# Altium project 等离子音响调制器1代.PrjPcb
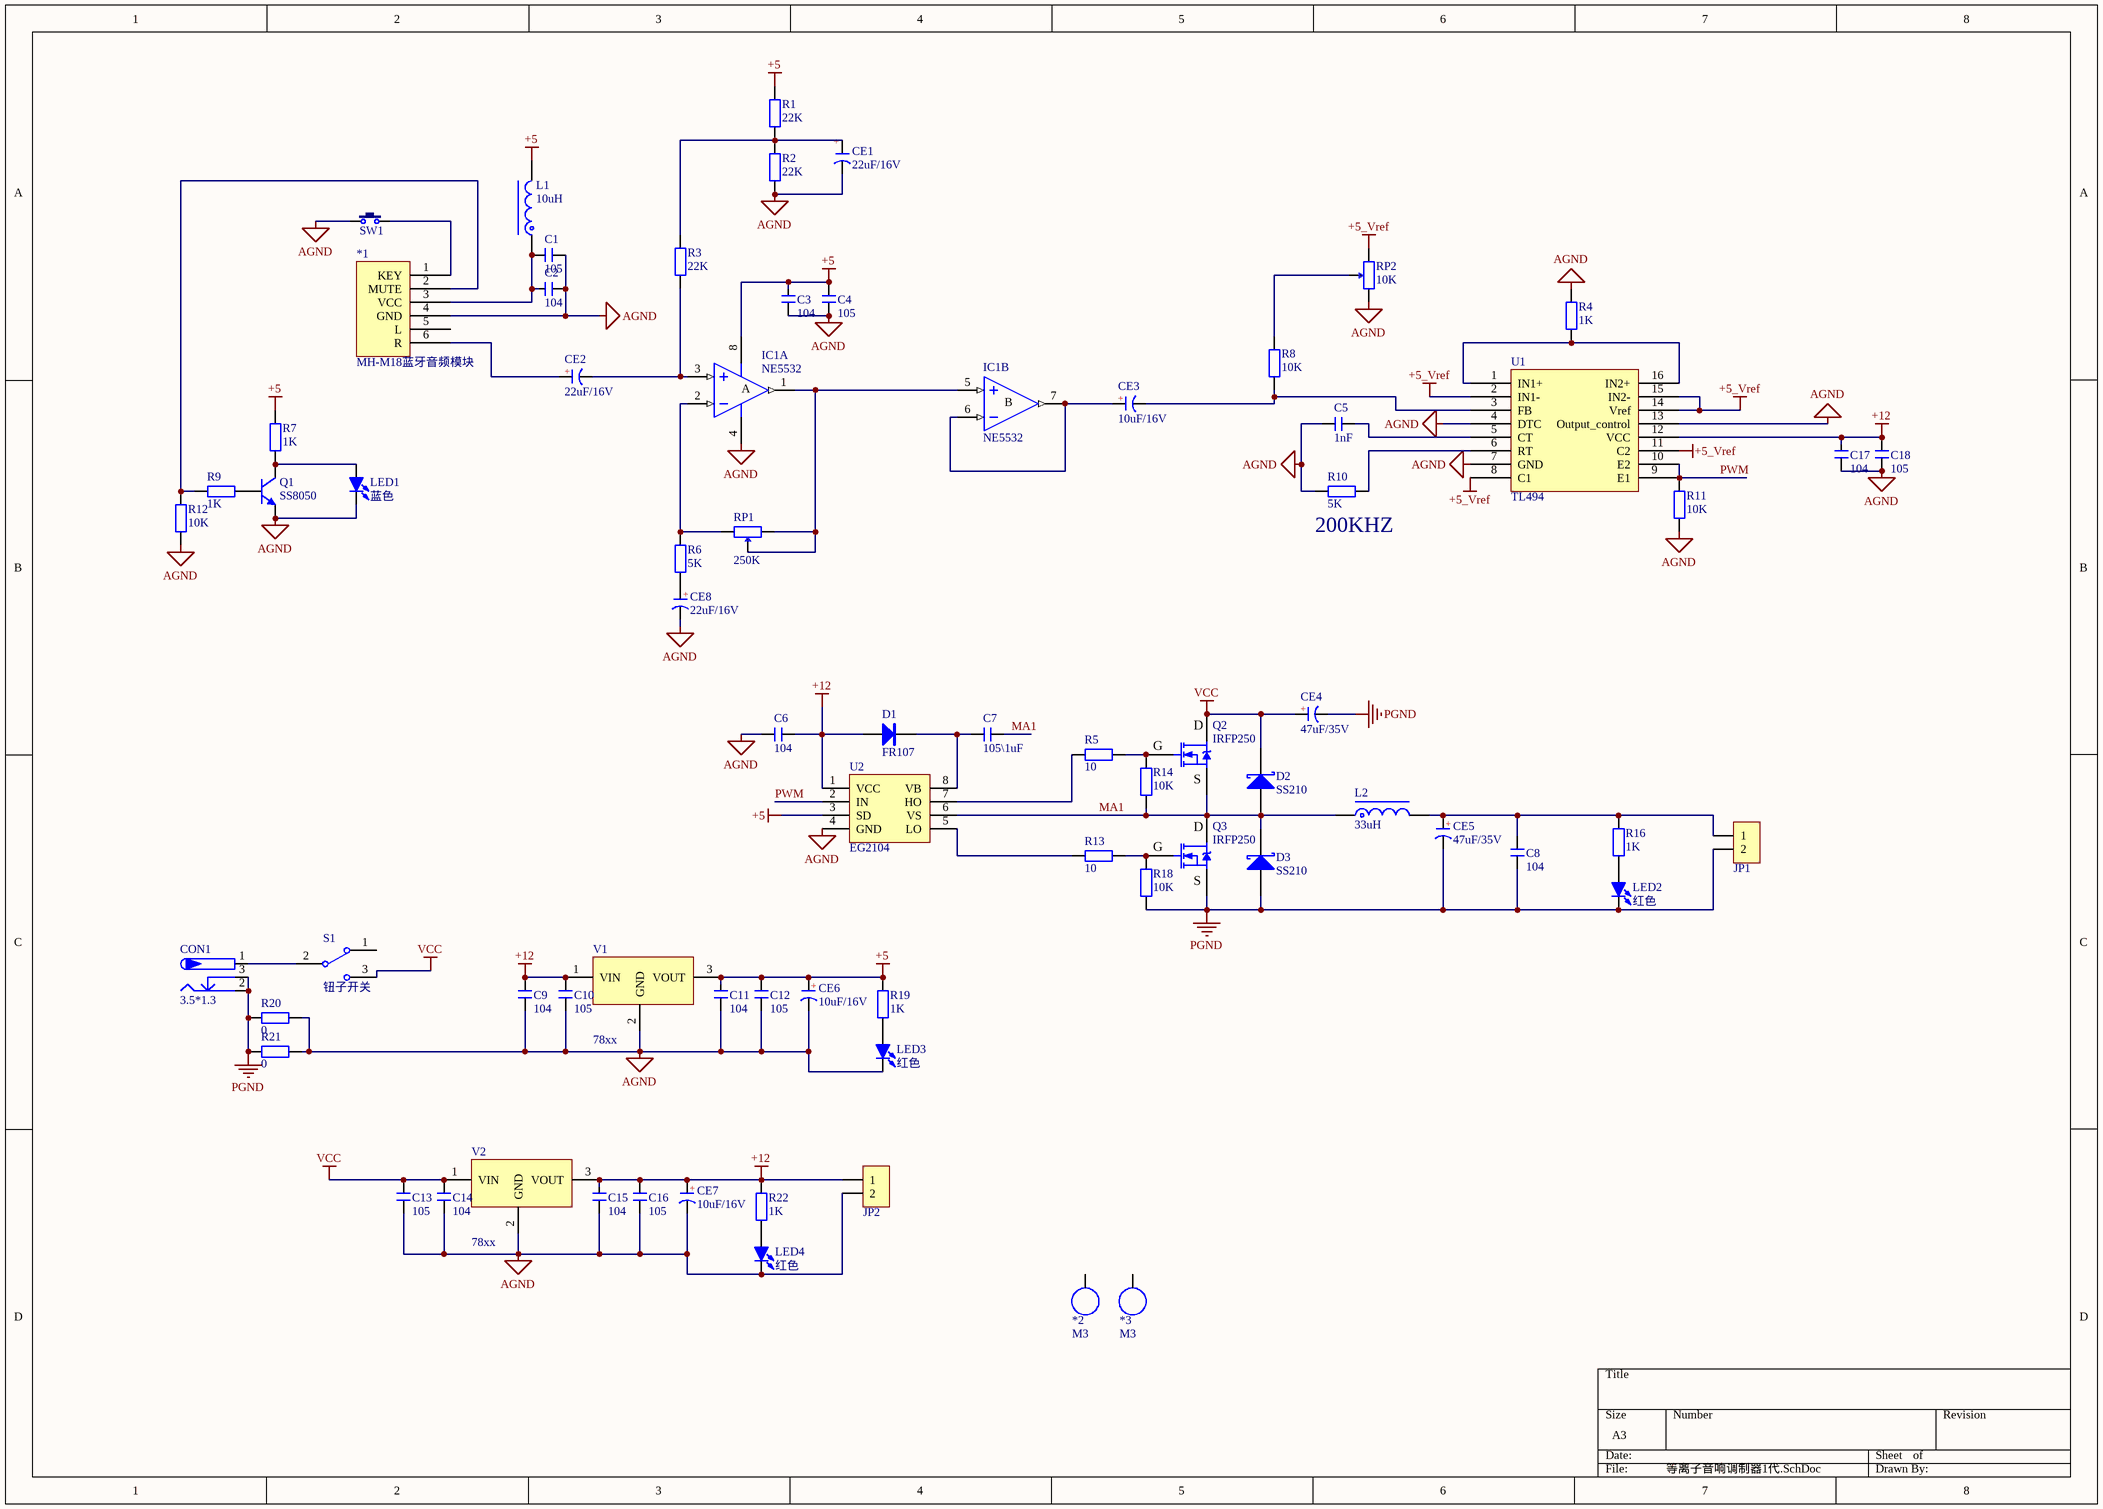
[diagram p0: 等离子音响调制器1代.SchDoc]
1 sheet, 73 parts. Net scope: global (net labels, ports and power ports of the same name join across sheets).
Board file: 等离子音响调制器.PcbDoc

## Sheet 等离子音响调制器1代.SchDoc
size A3; SheetNumber: 1; SheetTotal: 1

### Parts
*1  MH-M18蓝牙音频模块  [MH-M18蓝牙音频模块]
*2  M3  [M3 125X200]
*3  M3  [M3 125X200]
C1  105  [C 0805_L]
C2  104  [C 0603_L]
C3  104  [C 0603_L]
C4  105  [C 0805_L]
C5  1nF  [C 0603_L]
C6  104  [C 0603_L]
C7  105\1uF  [C 0805_L]
C8  104  [C 0805_L]
C9  104  [C 0603_L]
C10  105  [C 0805_L]
C11  104  [C 0603_L]
C12  105  [C 0805_L]
C13  105  [C 0805_L]
C14  104  [C 0603_L]
C15  104  [C 0603_L]
C16  105  [C 0805_L]
C17  104  [C 0603_L]
C18  105  [C 0805_L]
CE1  22uF/16V  [CAP 2.0*5*11]
CE2  22uF/16V  [CAP 2.0*5*11]
CE3  10uF/16V  [CAP 2.0*5*11]
CE4  47uF/35V  [CAP 5.0*10*12.5]
CE5  47uF/35V  [CAP 3.5*8*11.5]
CE6  10uF/16V  [CAP 3.5*8*11.5 - GD]
CE7  10uF/16V  [CAP 3.5*8*11.5 - GD]
CE8  22uF/16V  [CAP 2.0*5*11]
CON1  3.5*1.3  [DC-005]
D1  FR107  [SOD-123]
D2  SS210  [SMA]
D3  SS210  [SMA]
IC1  NE5532  [DIP8-300]  (parts A,B of 2)
JP1  HDR-1X2  [KF128-5.08-2P]  (value not drawn)
JP2  HDR-1X2  [XH2.54-LI-2P]  (value not drawn)
L1  10uH  [PK0810]
L2  33uH  [65125]
LED1  蓝色  [LED 0603Y]
LED2  红色  [LED 0603Y]
LED3  红色  [LED 0603Y]
LED4  红色  [LED 0603Y]
Q1  SS8050  [SOT23-3N]
Q2  IRFP250  [TO247A]
Q3  IRFP250  [TO247A]
R1  22K  [R 0603_L]
R2  22K  [R 0603_L]
R3  22K  [R 0603_L]
R4  1K  [R 0603_L]
R5  10  [RS 1/4W]
R6  5K  [R 0603_L]
R7  1K  [R 0603_L]
R8  10K  [R 0603_L]
R9  1K  [R 0603_L]
R10  5K  [R 0603_L]
R11  10K  [R 0603_L]
R12  10K  [R 0603_L]
R13  10  [RS 1/4W]
R14  10K  [RS 1/4W]
R16  1K  [R 0603_L]
R18  10K  [RS 1/4W]
R19  1K  [R 0603_L]
R20  0  [R 0603_L]
R21  0  [R 0603_L]
R22  1K  [R 0603_L]
RP1  250K  [3296W]
RP2  10K  [3296W]
S1  钮子开关  [MS-102-C4]
SW1  6x6x5  [TSW DIP-6*6*6_V]  (value not drawn)
U1  TL494  [DIP16-300_MH]
U2  EG2104  [SOP8]
V1  78xx  [TO220A]
V2  78xx  [TO220A]

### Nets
+5: C3.2 C4.2 C11.2 C12.2 CE6.1(A) IC1.8(V+) L1.2 R1.2 R7.1 R19.2 U2.3(SD) V1.3(VOUT)
+5_Vref: RP2.3 U1.2(IN1-) U1.8(C1) U1.11(C2) U1.14(Vref) U1.15(IN2-)
+12: C6.2 C9.2 C10.2 C15.2 C16.2 C17.2 C18.2 CE7.1(A) D1.1(A) JP2.1 R22.2 U1.12(VCC) U2.1(VCC) V1.1(VIN) V2.3(VOUT)
AGND: *1.4(GND) C1.1 C2.1 C3.1 C4.1 C5.2 C6.1 C9.1 C10.1 C11.1 C12.1 C13.1 C14.1 C15.1 C16.1 C17.1 C18.1 CE1.2(K) CE6.2(K) CE7.2(K) CE8.2(K) IC1.4(V-) JP2.2 LED1.2(K) LED3.2(K) LED4.2(K) Q1.2(E) R2.1 R4.1 R10.1 R11.2 R12.1 R20.2 R21.2 RP2.1 SW1.1 U1.4(DTC) U1.7(GND) U1.13(Output_control) U2.4(GND) V1.2(GND) V2.2(GND)
PGND: C8.2 CE4.2(K) CE5.2(K) CON1.2 CON1.3 D3.1(A) JP1.2 LED2.2(K) Q3.3(S) R18.1 R20.1 R21.1
VCC: C13.2 C14.2 CE4.1(A) D2.2(K) Q2.2(D) S1.3 V2.1(VIN)
MA1: C7.1 D2.1(A) D3.2(K) L2.1 Q2.3(S) Q3.2(D) R14.1 U2.6(VS)
PWM: R11.1 U1.9(E1) U1.10(E2) U2.2(IN)
Net*1_1: *1.1(KEY) SW1.2
Net*1_2: *1.2(MUTE) R9.2 R12.2
Net*1_3: *1.3(VCC) C1.2 C2.2 L1.1
Net*1_6: *1.6(R) CE2.1(A)
NetC5_1: C5.1 U1.5(CT)
NetC7_2: C7.2 D1.2(K) U2.8(VB)
NetC8_1: C8.1 CE5.1(A) JP1.1 L2.2 R16.2
NetCE1_1: CE1.1(A) R1.1 R2.2 R3.2
NetCE2_2: CE2.2(K) IC1.3(IN+) R3.1
NetCE3_1: CE3.1(A) IC1.6(IN-) IC1.7(OUT)
NetCE3_2: CE3.2(K) R8.1 U1.3(FB)
NetCE8_1: CE8.1(A) R6.2
NetCON1_1: CON1.1 S1.2
NetIC1_1: IC1.1(OUT) IC1.5(IN+) RP1.1 RP1.2
NetIC1_2: IC1.2(IN-) R6.1 RP1.3
NetLED1_1: LED1.1(A) Q1.3(C) R7.2
NetLED2_1: LED2.1(A) R16.1
NetLED3_1: LED3.1(A) R19.1
NetLED4_1: LED4.1(A) R22.1
NetQ1_1: Q1.1(B) R9.1
NetQ2_1: Q2.1(G) R5.1 R14.2
NetQ3_1: Q3.1(G) R13.1 R18.2
NetR4_2: R4.2 U1.1(IN1+) U1.16(IN2+)
NetR5_2: R5.2 U2.7(HO)
NetR8_2: R8.2 RP2.2
NetR10_2: R10.2 U1.6(RT)
NetR13_2: R13.2 U2.5(LO)

Not connected (* = marked no-connect by the designer): *1 5(L); *2 1; *3 1; S1 1

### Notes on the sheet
- (near R10) 200KHZ

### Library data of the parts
*2 *3 = M3: 铜柱孔; 版权归属: 封装库来自淘宝 ID：黄晶宝石
C1-C18 = C: 贴片电容; BOM名称: 无极性贴片电容; 淘宝ID: 封装库来自淘宝 ID：黄晶宝石
CE1-CE8 = CE: 直插电解电容; 淘宝ID: 封装库来自淘宝 ID：黄晶宝石
CON1 = P-DC: 低压电源接口; BOM名称: DC电源接口; 版权归属: 封装库来自淘宝 ID：黄晶宝石
D1 = FR107: 快恢复整流二极管; BOM名称: 快恢复二极管; 版权归属: 封装库来自淘宝 ID：黄晶宝石; 属性: 700V/1A
D2 D3 = SS210: 肖特基二极管
IC1 = NE5532: 双路低噪声音频运放; 版权归属: 封装库来自淘宝 ID：黄晶宝石
JP1 = Header 2: 2P接插件; 版权归属: 封装库来自淘宝卖家 ID：黄晶宝石
JP2 = Header 2: 2P接插件; 版权归属: 封装库来自淘宝 ID：黄晶宝石
L1 = L-PK: 工字电感; 淘宝ID: 来自淘宝 ID：黄晶宝石
L2 = L-MR: 功率磁环电感; 淘宝ID: 封装库来自淘宝 ID：黄晶宝石
LED1-LED4 = LED-SMD: 贴片LED; 版权归属: 封装库来自淘宝 ID：黄晶宝石
Q1 = 8050-SMD: 高频放大-NPN型; 版权归属: 封装库来自淘宝 ID：黄晶宝石; 属性: 40V 1.5A 1W 100MHZ
Q2 Q3 = IRFP250: 功率型N沟场效应管; 版权归属: 封装库来自淘宝卖家 ID：黄晶宝石
R1-R4 R6-R12 R16 R19-R22 = R: 贴片电阻; 版权归属: 来自淘宝 ID：黄晶宝石; 封装库来自淘宝卖家 ID：黄晶宝石: 其他店铺购入均为盗版，不享受售后技术支持服务，请立即申请退款
R5 R13 R14 R18 = R-S: 色环电阻; 版权归属: 封装库来自淘宝 ID：黄晶宝石
RP1 RP2 = RP: 单联电位器; BOM名称: 插件电位器; 版权归属: 封装库来自淘宝 ID：黄晶宝石
S1 = MTS-102
SW1 = TSW DIP-6x6_V: 侧按直插6x6轻触开关; 版权归属: 封装库来自淘宝 ID：黄晶宝石
U1 = TL494: 开关电源控制芯片
U2 = EG2104: 半桥驱动芯片
V1 V2 = 78xx: LM78XX系列线性稳压芯片; BOM名称: 线性稳压芯片; 淘宝ID: 封装库来自淘宝 ID：黄晶宝石; 技术支持，联系售后: 其他店铺购入均为盗版，不享受售后技术支持服务，请立即申请退款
